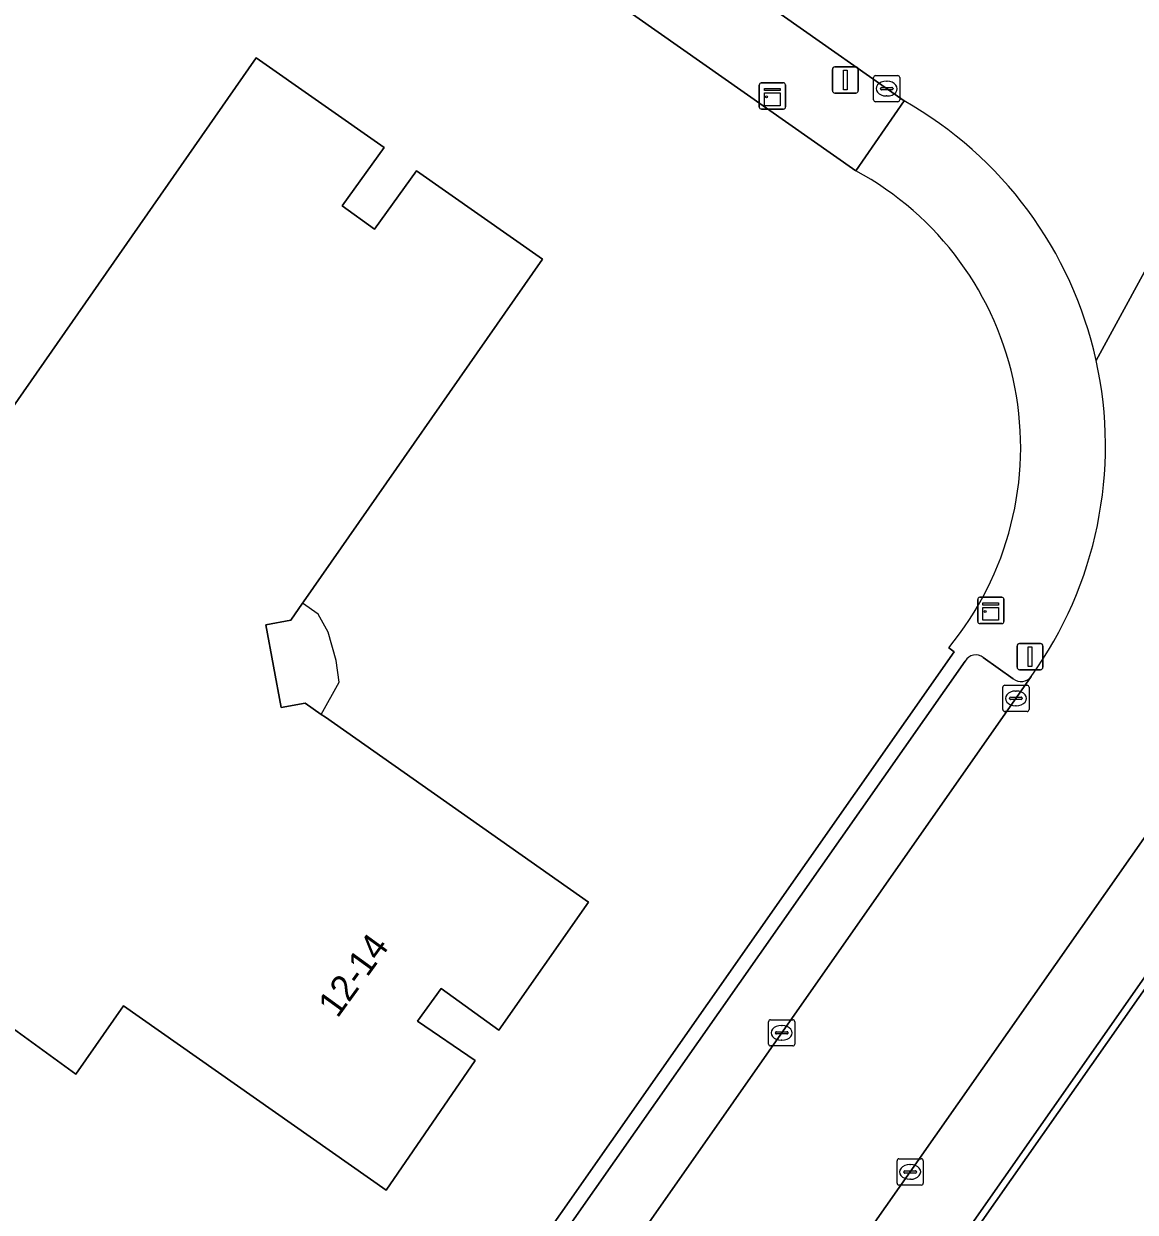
# Model space of a CAD drawing. Extents: x 155018 to 156648, y 383979 to 385733.
# Drawn here: x 155613.96 to 155656.36, y 384830.45 to 384875.78 of the extents above; entities that cross this region are included whole.
import ezdxf

# ---------------------------------------------------------------- set-up
doc = ezdxf.new("R2010")
doc.units = 0
for name, color, linetype in [('IMGEO_Erf', 7, 'Continuous'), ('IMGEO_Groenvoorziening', 7, 'Continuous'), ('IMGEO_Hek', 7, 'Continuous'), ('IMGEO_Kast', 7, 'Continuous'), ('IMGEO_Kolk', 7, 'Continuous'), ('IMGEO_Lichtmast', 7, 'Continuous'), ('IMGEO_Pand', 7, 'Continuous'), ('IMGEO_Pand_nummerreeks', 7, 'Continuous'), ('IMGEO_Pand_overbouw', 7, 'Continuous'), ('IMGEO_Parkeervlak_open', 7, 'Continuous'), ('IMGEO_Rijbaan_lokaal_gesloten', 7, 'Continuous'), ('IMGEO_Voetpad_open', 7, 'Continuous')]:
    doc.layers.add(name, color=color, linetype=linetype)

msp = doc.modelspace()

# ---------------------------------------------------------------- linework, layer by layer
at = {"layer": 'IMGEO_Erf'}
for points in [[(155730.975, 385018.536), (155724.402, 385000), (155719.139, 384985.171), (155718.598, 384983.687), (155716.009, 384976.585), (155715.7, 384975.738), (155702.844, 384939.771), (155702.172, 384937.868), (155696.786, 384922.628), (155696.12, 384920.743), (155684.958, 384889.381), (155684.425, 384889.57), (155682.806, 384885.06), (155682.424, 384883.902), (155681.972, 384882.563), (155681.138, 384880.234), (155681.15, 384879.519), (155676.547, 384866.454), (155676.35, 384866.575), (155669.497, 384856.797), (155669.212, 384856.331), (155667.198, 384853.508), (155667.02, 384853.625), (155588.106, 384741.158)], [(155645.703, 384870.176), (155613.715, 384892.628), (155600.657, 384901.793), (155582.308, 384914.778), (155574.917, 384919.981), (155570.133, 384923.483), (155539.854, 384944.743), (155535.161, 384948.038), (155534.984, 384948.163), (155531.101, 384950.889), (155530.5, 384951.311), (155510.828, 384965.124), (155506.264, 384968.328), (155505.588, 384968.803), (155501.395, 384971.747), (155500, 384972.727), (155492.047, 384978.311), (155491.266, 384978.86), (155482.605, 384984.76), (155482.381, 384984.92), (155460.927, 385000), (155450.653, 385007.222)], [(155612.652, 384859.899), (155622.834, 384874.486), (155627.714, 384871.061), (155626.105, 384868.833), (155627.341, 384867.949), (155628.945, 384870.173), (155633.755, 384866.804), (155624.637, 384853.733), (155624.601, 384853.681), (155624.151, 384853.036), (155623.199, 384852.852), (155623.782, 384849.701), (155624.701, 384849.87), (155625.313, 384849.44), (155625.473, 384849.328), (155635.511, 384842.28), (155632.089, 384837.394), (155629.882, 384838.983), (155628.984, 384837.743), (155631.189, 384836.244), (155627.787, 384831.294), (155617.772, 384838.326), (155615.948, 384835.721), (155613.296, 384837.652)], [(155553.633, 384715.232), (155553.739, 384715.172), (155553.747, 384715.183), (155566.056, 384732.66), (155578.198, 384750), (155612.129, 384798.458), (155612.508, 384798.198), (155616.168, 384803.406), (155615.737, 384803.696), (155649.459, 384851.832), (155649.247, 384851.98)]]:
    msp.add_lwpolyline(points, dxfattribs=at)
msp.add_arc((155639.992, 384859.621), 12.001, 320.4584, 61.5844, dxfattribs=at)
at = {"layer": 'IMGEO_Groenvoorziening'}
msp.add_lwpolyline([(155667.02, 384853.625), (155667.198, 384853.508), (155669.212, 384856.331), (155669.497, 384856.797), (155668.817, 384856.954), (155660.389, 384844.659), (155636.862, 384811.074), (155608.808, 384771.107), (155594.019, 384750), (155586.655, 384739.49), (155582.342, 384733.152), (155582.316, 384732.95), (155582.416, 384732.885), (155582.631, 384733.19), (155586.789, 384739.087), (155588.217, 384741.112), (155588.106, 384741.158)], close=True, dxfattribs=at)
at = {"layer": 'IMGEO_Hek'}
msp.add_lwpolyline([(155586.789, 384739.087), (155588.217, 384741.112), (155588.106, 384741.158), (155667.02, 384853.625), (155667.198, 384853.508), (155669.212, 384856.331)], dxfattribs=at)
at = {"layer": 'IMGEO_Kast'}
for p, q in [((155642.022, 384872.603), (155642.022, 384873.444)), ((155642.022, 384873.444), (155642.022, 384872.603)), ((155642.097, 384873.528), (155642.938, 384873.528)), ((155642.938, 384873.528), (155642.097, 384873.528)), ((155643.022, 384873.453), (155643.022, 384872.612)), ((155643.022, 384872.612), (155643.022, 384873.453)), ((155642.947, 384872.528), (155642.106, 384872.528)), ((155642.106, 384872.528), (155642.947, 384872.528)), ((155650.43, 384853.905), (155651.271, 384853.905)), ((155651.271, 384853.905), (155650.43, 384853.905)), ((155650.355, 384852.98), (155650.355, 384853.821)), ((155650.355, 384853.821), (155650.355, 384852.98)), ((155651.355, 384853.83), (155651.355, 384852.989)), ((155651.355, 384852.989), (155651.355, 384853.83)), ((155651.28, 384852.905), (155650.439, 384852.905)), ((155650.439, 384852.905), (155651.28, 384852.905))]:
    msp.add_line(p, q, dxfattribs=at)
for points in [[(155642.217, 384873.318), (155642.817, 384873.318), (155642.817, 384873.233), (155642.217, 384873.233), (155642.217, 384873.318)], [(155642.217, 384873.143), (155642.817, 384873.143), (155642.817, 384872.654), (155642.217, 384872.654), (155642.217, 384873.143)], [(155650.55, 384853.695), (155651.15, 384853.695), (155651.15, 384853.61), (155650.55, 384853.61), (155650.55, 384853.695)], [(155650.55, 384853.52), (155651.15, 384853.52), (155651.15, 384853.031), (155650.55, 384853.031), (155650.55, 384853.52)]]:
    msp.add_lwpolyline(points, dxfattribs=at)
for centre in [(155642.301, 384872.992), (155650.634, 384853.369)]:
    msp.add_circle(centre, 0.0377, dxfattribs=at)
for centre, start, end in [((155642.1, 384873.45), 92.4484, 184.2845), ((155642.1, 384873.45), 92.4484, 184.2845), ((155642.944, 384873.45), 2.4484, 94.2845), ((155642.944, 384873.45), 2.4484, 94.2845), ((155642.1, 384872.606), 182.4484, 274.2845), ((155642.1, 384872.606), 182.4484, 274.2845), ((155642.944, 384872.606), 272.4484, 4.2845), ((155642.944, 384872.606), 272.4484, 4.2845), ((155650.433, 384853.827), 92.4484, 184.2845), ((155650.433, 384853.827), 92.4484, 184.2845), ((155651.277, 384853.827), 2.4484, 94.2845), ((155651.277, 384853.827), 2.4484, 94.2845), ((155651.277, 384852.983), 272.4484, 4.2845), ((155651.277, 384852.983), 272.4484, 4.2845), ((155650.433, 384852.983), 182.4484, 274.2845), ((155650.433, 384852.983), 182.4484, 274.2845)]:
    msp.add_arc(centre, 0.0779, start, end, dxfattribs=at)
at = {"layer": 'IMGEO_Kolk'}
for p, q in [((155646.381, 384872.881), (155646.381, 384873.733)), ((155646.456, 384873.807), (155647.308, 384873.807)), ((155646.869, 384873.587), (155646.894, 384873.587)), ((155647.382, 384873.733), (155647.382, 384872.881)), ((155646.64, 384873.301), (155646.64, 384873.313)), ((155647.078, 384873.264), (155646.68, 384873.264)), ((155646.683, 384873.35), (155647.081, 384873.35)), ((155646.892, 384873.027), (155646.867, 384873.027)), ((155647.124, 384873.313), (155647.124, 384873.301)), ((155647.308, 384872.807), (155646.456, 384872.807)), ((155651.311, 384849.624), (155651.311, 384850.476)), ((155651.386, 384850.55), (155652.238, 384850.55)), ((155651.799, 384850.33), (155651.824, 384850.33)), ((155652.312, 384850.476), (155652.312, 384849.624)), ((155651.57, 384850.044), (155651.57, 384850.056)), ((155652.008, 384850.007), (155651.61, 384850.007)), ((155651.613, 384850.093), (155652.011, 384850.093)), ((155652.054, 384850.056), (155652.054, 384850.044)), ((155652.238, 384849.55), (155651.386, 384849.55)), ((155651.822, 384849.77), (155651.797, 384849.77)), ((155642.376, 384836.867), (155642.376, 384837.719)), ((155642.451, 384837.793), (155643.303, 384837.793)), ((155642.864, 384837.573), (155642.889, 384837.573)), ((155643.377, 384837.719), (155643.377, 384836.867)), ((155642.635, 384837.287), (155642.635, 384837.299)), ((155643.073, 384837.25), (155642.675, 384837.25)), ((155642.678, 384837.336), (155643.076, 384837.336)), ((155643.119, 384837.299), (155643.119, 384837.287)), ((155643.303, 384836.793), (155642.451, 384836.793)), ((155642.887, 384837.013), (155642.862, 384837.013)), ((155647.276, 384831.562), (155647.276, 384832.414)), ((155647.351, 384832.488), (155648.203, 384832.488)), ((155647.764, 384832.268), (155647.789, 384832.268)), ((155648.277, 384832.414), (155648.277, 384831.562)), ((155647.535, 384831.982), (155647.535, 384831.994)), ((155647.973, 384831.945), (155647.575, 384831.945)), ((155647.578, 384832.031), (155647.976, 384832.031)), ((155647.787, 384831.708), (155647.762, 384831.708)), ((155648.019, 384831.994), (155648.019, 384831.982)), ((155648.203, 384831.488), (155647.351, 384831.488))]:
    msp.add_line(p, q, dxfattribs=at)
for points in [[(155646.381, 384872.881), (155646.381, 384873.733)], [(155646.456, 384873.807), (155647.308, 384873.807)], [(155647.382, 384873.733), (155647.382, 384872.881)], [(155647.308, 384872.807), (155646.456, 384872.807)], [(155651.311, 384849.624), (155651.311, 384850.476)], [(155651.386, 384850.55), (155652.238, 384850.55)], [(155652.312, 384850.476), (155652.312, 384849.624)], [(155652.238, 384849.55), (155651.386, 384849.55)], [(155642.376, 384836.867), (155642.376, 384837.719)], [(155642.451, 384837.793), (155643.303, 384837.793)], [(155643.377, 384837.719), (155643.377, 384836.867)], [(155643.303, 384836.793), (155642.451, 384836.793)], [(155647.276, 384831.562), (155647.276, 384832.414)], [(155647.351, 384832.488), (155648.203, 384832.488)], [(155648.277, 384832.414), (155648.277, 384831.562)], [(155648.203, 384831.488), (155647.351, 384831.488)]]:
    msp.add_lwpolyline(points, dxfattribs=at)
for centre, radius, start, end in [((155646.458, 384873.731), 0.0765, 91.552, 178.448), ((155646.458, 384873.731), 0.0765, 91.552, 178.448), ((155647.306, 384873.731), 0.0765, 1.552, 88.448), ((155647.306, 384873.731), 0.0765, 1.552, 88.448), ((155646.68, 384873.31), 0.0403, 85.8775, 175.7526), ((155646.677, 384873.3), 0.0366, 178.938, 274.7102), ((155647.081, 384873.307), 0.043, 264.8664, 352.4533), ((155647.085, 384873.312), 0.0386, 1.7309, 96.639), ((155646.458, 384872.883), 0.0765, 181.552, 268.448), ((155646.458, 384872.883), 0.0765, 181.552, 268.448), ((155647.306, 384872.883), 0.0765, 271.552, 358.448), ((155647.306, 384872.883), 0.0765, 271.552, 358.448), ((155651.388, 384850.474), 0.0765, 91.552, 178.448), ((155651.388, 384850.474), 0.0765, 91.552, 178.448), ((155652.236, 384850.474), 0.0765, 1.552, 88.448), ((155652.236, 384850.474), 0.0765, 1.552, 88.448), ((155651.61, 384850.053), 0.0403, 85.8775, 175.7526), ((155651.607, 384850.043), 0.0366, 178.938, 274.7102), ((155652.011, 384850.05), 0.043, 264.8664, 352.4533), ((155652.015, 384850.055), 0.0386, 1.7309, 96.639), ((155651.388, 384849.626), 0.0765, 181.552, 268.448), ((155651.388, 384849.626), 0.0765, 181.552, 268.448), ((155652.236, 384849.626), 0.0765, 271.552, 358.448), ((155652.236, 384849.626), 0.0765, 271.552, 358.448), ((155642.453, 384837.717), 0.0765, 91.552, 178.448), ((155642.453, 384837.717), 0.0765, 91.552, 178.448), ((155643.301, 384837.717), 0.0765, 1.552, 88.448), ((155643.301, 384837.717), 0.0765, 1.552, 88.448), ((155642.675, 384837.296), 0.0403, 85.8775, 175.7526), ((155642.672, 384837.286), 0.0366, 178.938, 274.7102), ((155643.076, 384837.293), 0.043, 264.8664, 352.4533), ((155643.08, 384837.298), 0.0386, 1.7309, 96.639), ((155642.453, 384836.869), 0.0765, 181.552, 268.448), ((155642.453, 384836.869), 0.0765, 181.552, 268.448), ((155643.301, 384836.869), 0.0765, 271.552, 358.448), ((155643.301, 384836.869), 0.0765, 271.552, 358.448), ((155647.353, 384832.412), 0.0765, 91.552, 178.448), ((155647.353, 384832.412), 0.0765, 91.552, 178.448), ((155648.201, 384832.412), 0.0765, 1.552, 88.448), ((155648.201, 384832.412), 0.0765, 1.552, 88.448), ((155647.575, 384831.991), 0.0403, 85.8775, 175.7526), ((155647.572, 384831.981), 0.0366, 178.938, 274.7102), ((155647.976, 384831.988), 0.043, 264.8664, 352.4533), ((155647.98, 384831.993), 0.0386, 1.7309, 96.639), ((155647.353, 384831.564), 0.0765, 181.552, 268.448), ((155647.353, 384831.564), 0.0765, 181.552, 268.448), ((155648.201, 384831.564), 0.0765, 271.552, 358.448), ((155648.201, 384831.564), 0.0765, 271.552, 358.448)]:
    msp.add_arc(centre, radius, start, end, dxfattribs=at)
for centre, major_axis, ratio, start_param, end_param in [((155646.868, 384873.307), (-0.387, 0.002), 0.722429, 4.712389, 7.853982), ((155646.893, 384873.307), (-0.39, 0.002), 0.717154, 1.570796, 4.712389), ((155651.798, 384850.05), (-0.387, 0.002), 0.722429, 4.712389, 7.853982), ((155651.823, 384850.05), (-0.39, 0.002), 0.717154, 1.570796, 4.712389), ((155642.863, 384837.293), (-0.387, 0.002), 0.722429, 4.712389, 7.853982), ((155642.888, 384837.293), (-0.39, 0.002), 0.717154, 1.570796, 4.712389), ((155647.763, 384831.988), (-0.387, 0.002), 0.722429, 4.712389, 7.853982), ((155647.788, 384831.988), (-0.39, 0.002), 0.717154, 1.570796, 4.712389)]:
    msp.add_ellipse(centre, major_axis=major_axis, ratio=ratio, start_param=start_param, end_param=end_param, dxfattribs=at)
at = {"layer": 'IMGEO_Lichtmast'}
for p, q in [((155644.809, 384873.237), (155644.809, 384874.037)), ((155644.809, 384874.037), (155644.809, 384873.237)), ((155644.909, 384874.137), (155645.699, 384874.137)), ((155645.699, 384874.137), (155644.909, 384874.137)), ((155645.799, 384874.037), (155645.799, 384873.237)), ((155645.799, 384873.237), (155645.799, 384874.037)), ((155645.699, 384873.137), (155644.909, 384873.137)), ((155644.909, 384873.137), (155645.699, 384873.137)), ((155651.954, 384852.144), (155652.744, 384852.144)), ((155652.744, 384852.144), (155651.954, 384852.144)), ((155651.854, 384851.244), (155651.854, 384852.044)), ((155651.854, 384852.044), (155651.854, 384851.244)), ((155652.844, 384852.044), (155652.844, 384851.244)), ((155652.844, 384851.244), (155652.844, 384852.044)), ((155652.744, 384851.144), (155651.954, 384851.144)), ((155651.954, 384851.144), (155652.744, 384851.144))]:
    msp.add_line(p, q, dxfattribs=at)
for points in [[(155645.229, 384874.012), (155645.379, 384874.012), (155645.379, 384873.262), (155645.229, 384873.262), (155645.229, 384874.012)], [(155652.274, 384852.019), (155652.424, 384852.019), (155652.424, 384851.269), (155652.274, 384851.269), (155652.274, 384852.019)]]:
    msp.add_lwpolyline(points, dxfattribs=at)
for centre, start, end in [((155644.909, 384874.037), 90, 180), ((155644.909, 384874.037), 90, 180), ((155645.699, 384874.037), 0, 90), ((155645.699, 384874.037), 360, 90), ((155644.909, 384873.237), 180, 270), ((155644.909, 384873.237), 180, 270), ((155645.699, 384873.237), 270, 0), ((155645.699, 384873.237), 270, 0), ((155651.954, 384852.044), 90, 180), ((155651.954, 384852.044), 90, 180), ((155652.744, 384852.044), 0, 90), ((155652.744, 384852.044), 360, 90), ((155651.954, 384851.244), 180, 270), ((155651.954, 384851.244), 180, 270), ((155652.744, 384851.244), 270, 0), ((155652.744, 384851.244), 270, 0)]:
    msp.add_arc(centre, 0.1, start, end, dxfattribs=at)
at = {"layer": 'IMGEO_Pand'}
msp.add_lwpolyline([(155613.296, 384837.652), (155615.948, 384835.721), (155617.772, 384838.326), (155627.787, 384831.294), (155631.189, 384836.244), (155628.984, 384837.743), (155629.882, 384838.983), (155632.089, 384837.394), (155635.511, 384842.28), (155625.473, 384849.328), (155625.313, 384849.44), (155624.701, 384849.87), (155623.782, 384849.701), (155623.199, 384852.852), (155624.151, 384853.036), (155624.601, 384853.681), (155624.637, 384853.733), (155633.755, 384866.804), (155628.945, 384870.173), (155627.341, 384867.949), (155626.105, 384868.833), (155627.714, 384871.061), (155622.834, 384874.486), (155612.652, 384859.899)], dxfattribs=at)
at = {"layer": 'IMGEO_Pand_overbouw'}
msp.add_lwpolyline([(155624.601, 384853.681), (155624.151, 384853.036), (155623.199, 384852.852), (155623.782, 384849.701), (155624.701, 384849.87), (155625.313, 384849.44), (155625.995, 384850.666), (155625.887, 384851.499), (155625.58, 384852.57), (155625.196, 384853.26)], close=True, dxfattribs=at)
at = {"layer": 'IMGEO_Parkeervlak_open'}
for points in [[(155649.878, 384851.473), (155627.894, 384820.122), (155617.739, 384805.63), (155618.908, 384804.799), (155619.716, 384804.252), (155629.679, 384818.438), (155652.394, 384850.88)], [(155651.71, 384850.802), (155650.564, 384851.608)]]:
    msp.add_lwpolyline(points, dxfattribs=at)
for centre, radius, start, end in [((155650.28, 384851.24), 0.465, 52.3376, 149.9287), ((155652.015, 384851.168), 0.477, 230.2591, 322.7522)]:
    msp.add_arc(centre, radius, start, end, dxfattribs=at)
at = {"layer": 'IMGEO_Rijbaan_lokaal_gesloten'}
for points in [[(155452.478, 385009.864), (155466.537, 385000), (155468.855, 384998.374), (155481.303, 384989.599), (155484.226, 384987.538), (155493.798, 384980.798), (155500, 384976.456), (155502.879, 384974.44), (155503.149, 384974.25), (155507.358, 384971.292), (155508.017, 384970.829), (155512.594, 384967.613), (155532.25, 384953.8), (155532.882, 384953.356), (155536.732, 384950.651), (155536.91, 384950.526), (155541.6, 384947.23), (155571.894, 384925.942), (155573.015, 384925.172), (155576.741, 384922.577), (155602.522, 384904.454), (155615.591, 384895.277), (155647.55, 384872.837)], [(155654.873, 384862.94), (155662.924, 384877.712)], [(155662.924, 384877.712), (155654.873, 384862.94)], [(155557.839, 384704.064), (155557.967, 384704.242), (155558.339, 384703.973), (155565.165, 384713.55), (155573.586, 384725.999), (155578.096, 384732.463), (155583.356, 384740.042), (155586.289, 384744.214), (155590.343, 384750), (155608.173, 384775.45), (155620.847, 384793.568), (155634.39, 384812.919), (155647.778, 384831.987), (155658, 384846.57), (155663.285, 384854.104), (155665.547, 384857.446), (155665.874, 384857.967)], [(155652.394, 384850.88), (155629.679, 384818.438), (155619.716, 384804.252), (155613.015, 384794.672), (155602.107, 384779.088), (155598.478, 384773.909), (155581.725, 384750), (155573.395, 384738.09), (155569.504, 384732.554), (155555.663, 384712.8)]]:
    msp.add_lwpolyline(points, dxfattribs=at)
for centre, radius, start, end in [((155640.129, 384859.688), 15.098, 12.4368, 60.5602), ((155640.122, 384859.687), 15.105, 324.3338, 12.4348)]:
    msp.add_arc(centre, radius, start, end, dxfattribs=at)
at = {"layer": 'IMGEO_Voetpad_open'}
for points in [[(155615.591, 384895.277), (155602.522, 384904.454), (155576.741, 384922.577), (155574.917, 384919.981), (155582.308, 384914.778), (155600.657, 384901.793), (155613.715, 384892.628), (155645.703, 384870.176), (155647.55, 384872.837)], [(155586.655, 384739.49), (155594.019, 384750), (155608.808, 384771.107), (155636.862, 384811.074), (155660.389, 384844.659), (155668.817, 384856.954), (155665.874, 384857.967), (155665.547, 384857.446), (155663.285, 384854.104), (155658, 384846.57), (155647.778, 384831.987), (155634.39, 384812.919), (155620.847, 384793.568), (155608.173, 384775.45), (155590.343, 384750), (155586.289, 384744.214)]]:
    msp.add_lwpolyline(points, close=True, dxfattribs=at)
for points in [[(155647.55, 384872.837), (155645.703, 384870.176)], [(155649.247, 384851.98), (155649.459, 384851.832), (155615.737, 384803.696), (155616.168, 384803.406), (155616.394, 384803.727), (155616.33, 384803.906), (155617.539, 384805.599), (155617.739, 384805.63), (155627.894, 384820.122), (155649.878, 384851.473)], [(155650.564, 384851.608), (155651.71, 384850.802)]]:
    msp.add_lwpolyline(points, dxfattribs=at)
for centre, radius, start, end in [((155640.129, 384859.688), 15.098, 12.4368, 60.5602), ((155639.992, 384859.621), 12.001, 320.4584, 61.5844), ((155640.122, 384859.687), 15.105, 324.3338, 12.4348), ((155650.28, 384851.24), 0.465, 52.3376, 149.9287), ((155652.015, 384851.168), 0.477, 230.2591, 322.7522)]:
    msp.add_arc(centre, radius, start, end, dxfattribs=at)

# ---------------------------------------------------------------- texts
at = {"layer": 'IMGEO_Pand_nummerreeks'}
msp.add_text('12-14', height=1, rotation=54.0872, dxfattribs=at).set_placement((155625.929, 384837.822))

doc.saveas('drawing.dxf')
